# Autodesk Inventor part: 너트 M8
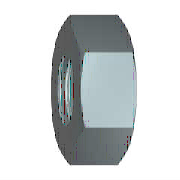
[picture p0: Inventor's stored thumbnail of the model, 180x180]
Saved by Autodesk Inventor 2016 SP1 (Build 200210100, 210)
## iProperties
IsCustomPart: 1
Created: 2012-02
Part Number: 너트 M8
Material: 강철, 연강
Description: 6각 너트 및 6각 가는 너트
Document SubType Name: Modeling
Standard: KS B 1012
Designer: mduedu
Standards Organization: KS
Language: ko-KR
Size Designation: M 8
Categories: <MemberInstance><Categories><Category DisplayName="조임쇠" InternalName="e4da775c-781d-43d5-af7c-5136215cf5a6" Mnemonic="FSTN"><Category DisplayName="너트" InternalN
Density: 1 g/cm^3
Appearance: 강철
Author: mduedu
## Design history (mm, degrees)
sketch "스케치1"
  geometry: L1 (-7.506, 0)-(-3.753, 6.5); L2 (-3.753, 6.5)-(3.753, 6.5); L3 (3.753, 6.5)-(7.506, 0); L4 (7.506, 0)-(3.753, -6.5); L5 (3.753, -6.5)-(-3.753, -6.5); L6 (-3.753, -6.5)-(-7.506, 0); 2 further points
  constraints: 12 end point, 1 coincident, 1 horizontal, 11 other
  dimensions: "d0" = 15.01111 distance of L3.end L1.start (= 1.1547 x SW)
extrude "본체" new body sketch "스케치1" distance "d1" = 5 (= KOH); taper "d2" = 0 deg
sketch "스케치2"
  geometry: L1 (0, 3.753)-(0, 7.506) reference; L2 (0, 7.506)-(5, 7.506) reference; L3 (5, 3.753)-(5, 7.506) reference; L4 (-1, 0)-(6, 0) reference; L5 (0.581, 7.506)-(0, 6.5); L6 (4.419, 7.506)-(5, 6.5)
  constraints: 4 end point, 4 point on line
  dimensions: "d3" = 30 deg angle of L1 L5 (= ANG1); "d4" = 30 deg angle of L3 L6 (= ANG2); "d5" = 13 diameter of L5.end L4 (= SW0); "d6" = 13 diameter of L6.end L4 (= SW01)
revolve "모따기1" sketch "스케치2" stored, may be unused: angle "d7" = 90 deg
sketch "스케치3"
  geometry: A1 r 6.5 centre (0, 0) between (-3.25, -5.629) and (3.25, -5.629) reference; 1 further point
  constraints: 1 coincident
hole "스레드" sketch "스케치3" at (0, 0) diameter "d25" = 6.647; stored, may be unused: countersink angle "d29" = 82 deg, drill point angle "d31" = 118 deg; dims "d26" = 6, "d27" = 4, "d28" = 2, "d30" = 8
workaxis "Work Axis1"
workplane "Work Plane1"
body "Solid1"
chamfer "모따기2" distance "d8" = 0.67658 (= -0.5 x GD1 + 0.5 x NND); stored, may be unused: angle "d9" = 30 deg, second distance "d40" = 0.67658 (= -0.5 x GD1 + 0.5 x NND)
chamfer "모따기3" distance "d10" = 0.67658 (= -0.5 x GD1 + 0.5 x NND); stored, may be unused: angle "d11" = 30 deg, second distance "d41" = 0.67658 (= -0.5 x GD1 + 0.5 x NND)
other parameters: "ANG1" = 30 deg [user parameter; used in 1 equation term], "ANG2" = 30 deg [user parameter; used in 1 equation term], "NND" = 8 [user parameter; used in 4 equation terms], "KOH" = 5 [user parameter; used in 1 equation term], "SW" = 13 [user parameter; used in 4 equation terms], "SW0" = 13 (= SW) [user parameter; used in 1 equation term], "SW01" = 13 (= SW) [user parameter; used in 1 equation term], "GD1" = 6.64684 (computed from THREADDIA, PTC, TOA) [user parameter; used in 4 equation terms], "d13" = 0, "d14" = 0, "d39" = 0, "d42" = 0, "GUL" = 0.67658 (= 0.541266 x PTC) [user parameter], "TPU" = 8 (computed from PTC) [user parameter], "THREADDIA" = 8 [user parameter; used in 1 equation term], "TOA" = 30 deg [user parameter; used in 1 equation term], "PTC" = 1.25 [user parameter; used in 4 equation terms], "E0" = 15.015 (= 1.155 x SW) [user parameter], "GAL" = 0.67658 (= 0.541266 x PTC) [user parameter]
